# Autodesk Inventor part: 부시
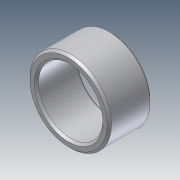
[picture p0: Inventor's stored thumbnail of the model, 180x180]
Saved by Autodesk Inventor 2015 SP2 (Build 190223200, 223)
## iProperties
Company: 한국ATC센터
Created: 2013-01
Part Number: 부시
Document SubType Name: Modeling
Designer: KYOUNG IL JANG
Density: 1 g/cm^3
Material: 일반
Appearance: 기본값
Author: KYOUNG IL JANG
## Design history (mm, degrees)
sketch "스케치1"
  geometry: L1 (15, 20)-(15, -46) reference; L2 (-20, 19)-(20, 19); L3 (30.7, -1)-(-30.7, -1) reference; L4 (19, 19)-(19, -1); L5 (15, -1)-(19, -1); L6 (0, 0)-(0, 19); L7 (19, 19)-(15, 19)
  constraints: 12 end point, 6 point on line, 1 collinear, 1 midpoint, 1 perpendicular, 1 vertical, 2 other
  dimensions: "d0" = 38 diameter of L4 L6; "d5" = 20 distance between parallel lines of L2 L3
revolve "회전1" sketch "스케치1" stored, may be unused: angle "d1" = 90 deg
chamfer "모따기1" distance "d2" = 1; stored, may be unused: second distance "d3" = 2, angle "d4" = 45 deg
node "솔리드1"
node "참조2"
